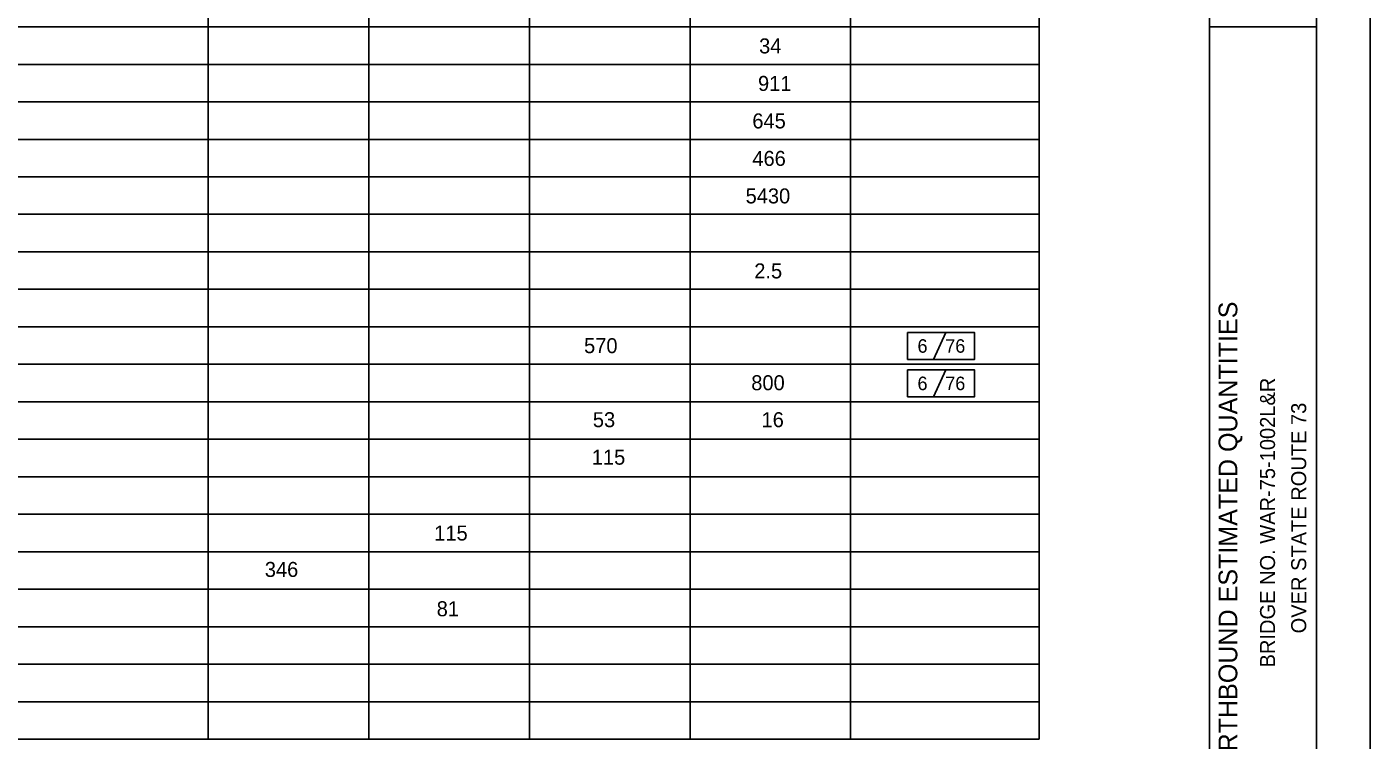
# Model space of a CAD drawing. Extents: x 0 to 34, y 0 to 22.
# Drawn here: x 21.46 to 34, y 7.34 to 14 of the extents above; entities that cross this region are included whole.
import ezdxf

# ---------------------------------------------------------------- set-up
doc = ezdxf.new("R2010")
doc.units = 0
for name, color, linetype in [('BR_P_Gen_Text', 7, 'Continuous'), ('SH_Border', 7, 'Continuous'), ('SH_Cut_Line', 7, 'Continuous'), ('SH_Data', 7, 'Continuous'), ('SH_Text', 7, 'Continuous')]:
    doc.layers.add(name, color=color, linetype=linetype)

msp = doc.modelspace()

# ---------------------------------------------------------------- linework, layer by layer
at = {"layer": 'BR_P_Gen_Text'}
for p, q in [((30.038, 11.146), (29.923, 10.896)), ((30.038, 10.797), (29.923, 10.547))]:
    msp.add_line(p, q, dxfattribs=at)
for points in [[(29.681, 11.146), (30.307, 11.146), (30.307, 10.896), (29.681, 10.896)], [(29.681, 11.146), (30.307, 11.146), (30.307, 10.896), (29.681, 10.896)], [(29.681, 10.797), (30.307, 10.797), (30.307, 10.547), (29.681, 10.547)], [(29.681, 10.797), (30.307, 10.797), (30.307, 10.547), (29.681, 10.547)]]:
    msp.add_lwpolyline(points, close=True, dxfattribs=at)
at = {"layer": 'SH_Border'}
for p, q in [((32.5, 0.5), (32.5, 21.5)), ((32.5, 0.5), (32.5, 21.5)), ((32.5, 0.5), (32.5, 21.5)), ((32.5, 14), (33.5, 14)), ((32.5, 14), (33.5, 14)), ((32.5, 14), (33.5, 14))]:
    msp.add_line(p, q, dxfattribs=at)
msp.add_lwpolyline([(2, 21.5), (33.5, 21.5), (33.5, 0.5), (2, 0.5)], close=True, dxfattribs=at)
at = {"layer": 'SH_Cut_Line'}
msp.add_lwpolyline([(0, 22), (34, 22), (34, 0), (0, 0)], close=True, dxfattribs=at)
at = {"layer": 'SH_Text'}
for p, q in [((30.91, 20.207), (30.91, 7.35)), ((23.15, 19.25), (23.15, 7.35)), ((24.65, 19.25), (24.65, 7.35)), ((26.15, 19.25), (26.15, 7.35)), ((27.65, 19.25), (27.65, 7.35)), ((29.15, 19.25), (29.15, 7.35)), ((3.59, 14), (30.91, 14)), ((3.59, 13.65), (30.91, 13.65)), ((3.59, 13.3), (30.91, 13.3)), ((3.59, 12.95), (30.91, 12.95)), ((3.59, 12.6), (30.91, 12.6)), ((3.59, 12.25), (30.91, 12.25)), ((3.59, 11.9), (30.91, 11.9)), ((3.59, 11.55), (30.91, 11.55)), ((3.59, 11.2), (30.91, 11.2)), ((3.59, 10.85), (30.91, 10.85)), ((3.59, 10.5), (30.91, 10.5)), ((3.59, 10.15), (30.91, 10.15)), ((3.59, 9.8), (30.91, 9.8)), ((3.59, 9.45), (30.91, 9.45)), ((3.59, 9.1), (30.91, 9.1)), ((3.59, 8.75), (30.91, 8.75)), ((3.59, 8.4), (30.91, 8.4)), ((3.59, 8.05), (30.91, 8.05)), ((3.59, 7.7), (30.91, 7.7)), ((3.59, 7.35), (30.91, 7.35))]:
    msp.add_line(p, q, dxfattribs=at)

# ---------------------------------------------------------------- texts
at = {"layer": 'BR_P_Gen_Text'}
for s, height, p in [('6', 0.126, (29.774, 10.958)), ('76', 0.1259, (30.033, 10.958)), ('6', 0.126, (29.774, 10.609)), ('76', 0.1259, (30.033, 10.609))]:
    msp.add_text(s, height=height, dxfattribs=at).set_placement(p)
at = {"layer": 'SH_Data'}
for s, height, p in [('     NORTHBOUND ESTIMATED QUANTITIES    ', 0.175, (32.76, 6.56)), ('BRIDGE NO. WAR-75-1002L&R', 0.14, (33.112, 8.02)), ('OVER STATE ROUTE 73', 0.14, (33.403, 8.338))]:
    msp.add_text(s, height=height, rotation=90, dxfattribs=at).set_placement(p)
at = {"layer": 'SH_Text'}
for s, p in [('34', (28.295, 13.752)), ('911', (28.285, 13.402)), ('645', (28.232, 13.052)), ('466', (28.232, 12.702)), ('5430', (28.169, 12.352)), ('2.5', (28.25, 11.652)), ('570', (26.661, 10.954)), ('800', (28.222, 10.608)), ('53', (26.743, 10.263)), ('16', (28.318, 10.263)), ('115', (26.733, 9.913)), ('115', (25.262, 9.205)), ('346', (23.68, 8.865)), ('81', (25.285, 8.498))]:
    msp.add_text(s, height=0.14, dxfattribs=at).set_placement(p)

doc.saveas('drawing.dxf')
